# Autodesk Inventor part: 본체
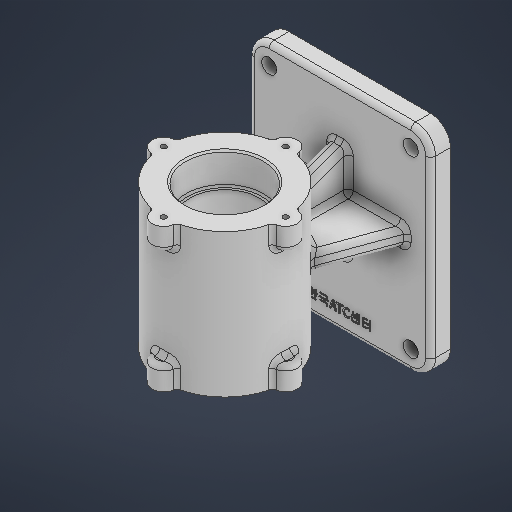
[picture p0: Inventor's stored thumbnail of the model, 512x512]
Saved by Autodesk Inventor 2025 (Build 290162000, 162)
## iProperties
Created: 2025-08
Part Number: 본체
Material: 일반
Document SubType Name: Modeling
Designer: infra14
Density: 1 g/cm^3
Appearance: 기본값
Author: infra14
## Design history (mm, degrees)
sketch "스케치1"
  geometry: L1 (55, -65)-(-55, -65); L2 (-55, -65)-(-55, 65); L3 (-55, 65)-(55, 65); L4 (55, 65)-(55, -65); L5 (55, -65)-(-55, 65); L6 (-55, -65)-(55, 65); 1 further point
  constraints: 12 end point, 2 midpoint, 2 parallel, 1 horizontal, 1 perpendicular
  dimensions: "d0" = 110 distance of L2.end L3.end; "d1" = 130 distance of L1.end L2.end
extrude "돌출1" new body sketch "스케치1" distance "d2" = 12; taper "d3" = 0 deg
sketch "스케치2"
  geometry: L1 (43, -53)-(-43, -53); L2 (-43, -53)-(-43, 53); L3 (-43, 53)-(43, 53); L4 (43, 53)-(43, -53); L5 (43, -53)-(-43, 53); L6 (-43, -53)-(43, 53); C1 r 4.5 at (-43, 53); C2 r 4.5 at (43, 53); C3 r 4.5 at (-43, -53); C4 r 4.5 at (43, -53); 1 further point
  constraints: 12 end point, 4 centre point, 4 coincident, 2 midpoint, 2 parallel, 1 horizontal, 1 perpendicular
  dimensions: "d4" = 86 distance of L2.end L3.end; "d5" = 106 distance of L1.end L2.end; "d6" = 9 diameter of C1; "d7" = 9 diameter of C2; "d8" = 9 diameter of C3; "d9" = 9 diameter of C4
extrude "돌출2" cut sketch "스케치2" distance "d10" = 12; taper "d11" = 0 deg
sketch "스케치3"
  geometry: L1 (29.5, 82)-(-19.5, 82); L2 (-19.5, 82)-(-19.5, 103); L3 (-19.5, 103)-(29.5, 103); L4 (29.5, 103)-(29.5, 82); L5 (-65, 0)-(-65, 12) reference; L6 (-65, 0)-(65, 0) reference; L7 (-19.5, 82)-(-38.5, 82); L8 (-38.5, 82)-(-38.5, 105.5); L9 (-38.5, 105.5)-(-19.5, 105.5); L10 (-19.5, 105.5)-(-19.5, 82); L11 (29.5, 82)-(48.5, 82); L12 (48.5, 82)-(48.5, 105.5); L13 (48.5, 105.5)-(29.5, 105.5); L14 (29.5, 105.5)-(29.5, 82); L15 (-38.5, 82)-(48.5, 82); L16 (48.5, 82)-(48.5, 119); L17 (48.5, 119)-(-38.5, 119); L18 (-38.5, 119)-(-38.5, 82); 7 further points
  constraints: 32 end point, 8 parallel, 4 horizontal, 4 perpendicular, 2 midpoint
  dimensions: "d12" = 49 distance of L2.end L3.end; "d13" = 21 distance of L1.end L2.end; "d14" = 70 distance from line of point (5, 103) L5; "d16" = 19 distance of L8.end L9.end; "d17" = 23.5 distance of L7.end L8.end; "d18" = 19 distance of L13.end L12.end; "d19" = 23.5 distance of L12.end L11.end; "d20" = 37 distance of L16.end L15.end; "d64" = 82 distance from line of L6 L1.start
revolve "회전1" sketch "스케치3" stored, may be unused: angle "d21" = 90 deg
sketch "스케치4"
  geometry: C1 r 7 at (0, 37); C2 r 7 at (-37, 0); C3 r 7 at (0, -37); C4 r 7 at (37, 0); 10 further points
  constraints: 4 centre point, 1 vertical alignment, 11 other
  dimensions: "d22" = 14 diameter of C1; "d25" = 360 deg dimension on point (0, 0) C1.centre (derived)
extrude "돌출3" join sketch "스케치4" distance "d27" = 14; taper "d28" = 0 deg
sketch "스케치6"
  geometry: A1 r 7 centre (0, -37) between (-6.969, -36.338) and (6.969, -36.338) reference; A2 r 7 centre (37, 0) between (36.338, -6.969) and (36.338, 6.969) reference; A3 r 7 centre (-37, 0) between (-36.338, 6.969) and (-36.338, -6.969) reference; A4 r 7 centre (0, 37) between (6.969, 36.338) and (-6.969, 36.338) reference; 2 further points
  constraints: 1 other
extrude "돌출4" join sketch "스케치6" distance "d29" = 14; taper "d30" = 0 deg
sketch "스케치8"
  geometry: A1 r 37 centre (0, 37) between (-6.969, 0.662) and (6.969, 0.662) reference; A2 r 37 centre (0, 37) between (36.338, 30.031) and (36.338, 43.969) reference; A3 r 37 centre (0, 37) between (6.969, 73.338) and (-6.969, 73.338) reference; A4 r 37 centre (0, 37) between (-36.338, 43.969) and (-36.338, 30.031) reference; 5 further points
  constraints: 8 point on circle
hole "구멍1" sketch "스케치8" at (0, 0), (37, 37), (0, 74), (-37, 37) diameter "d31" = 3.242; stored, may be unused: countersink angle "d35" = 90 deg, drill point angle "d37" = 118 deg; dims "d32" = 8, "d33" = 4, "d34" = 2, "d36" = 10
sketch "스케치9"
  geometry: A1 r 37 centre (0, -37) between (-6.969, -73.338) and (6.969, -73.338) reference; A2 r 37 centre (0, -37) between (-36.338, -30.031) and (-36.338, -43.969) reference; A3 r 7 centre (0, 0) between (6.969, -0.662) and (-6.969, -0.662) reference; A4 r 37 centre (0, -37) between (6.969, -0.662) and (-6.969, -0.662) reference; A5 r 37 centre (0, -37) between (36.338, -43.969) and (36.338, -30.031) reference; 5 further points
  constraints: 6 point on circle, 1 coincident
hole "구멍2" sketch "스케치9" at (0, -74), (-37, -37), (0, 0), (37, -37) diameter "d38" = 3.242; stored, may be unused: countersink angle "d42" = 90 deg, drill point angle "d44" = 118 deg; dims "d39" = 8, "d40" = 4, "d41" = 2, "d43" = 10
sketch "스케치11"
  geometry: L1 (34.5, 45)-(-24.5, 45) reference; L2 (-12.989, 45)-(-25, 12); L3 (65, 12)-(-65, 12) reference; L4 (35, 12)-(22.989, 45); L5 (-12.989, 45)-(22.989, 45); 2 further points
  constraints: 6 end point, 4 point on line, 2 midpoint, 1 collinear
  dimensions: "d45" = 110 deg angle of L3 L2; "d46" = 110 deg angle of L3 L4; "d47" = 60 distance of L4.start L2.end
extrude "돌출5" join sketch "스케치11" stored distance "d48" = 10; taper "d49" = 0 deg
node "작업 평면1"
sketch "스케치15"
  geometry: L1 (14, 12)-(29.664, 55.036); L2 (0, 0)-(110, 0) reference; L3 (0, 12)-(110, 12) reference; L4 (50, 45)-(50, 12) reference; L5 (50, 12)-(50, 45) reference; A1 r 37 centre (55, 82) between (48.031, 45.662) and (61.969, 45.662) reference; A2 r 37 centre (55, 82) between (18.662, 75.031) and (48.031, 45.662) reference; A3 r 37 centre (55, 82) between (18.662, 88.969) and (18.662, 75.031) reference; A4 r 37 centre (55, 82) between (48.031, 118.338) and (18.662, 88.969) reference; A5 r 37 centre (55, 82) between (61.969, 118.338) and (48.031, 118.338) reference; A6 r 37 centre (55, 82) between (91.338, 88.969) and (61.969, 118.338) reference; A7 r 37 centre (55, 82) between (91.338, 75.031) and (91.338, 88.969) reference; A8 r 37 centre (55, 82) between (61.969, 45.662) and (91.338, 75.031) reference; A9 r 37 centre (55, 82) between (18.662, 88.969) and (18.662, 75.031) reference; A10 r 37 centre (55, 82) between (18.662, 75.031) and (48.031, 45.662) reference; A11 r 37 centre (55, 82) between (48.031, 45.662) and (61.969, 45.662) reference; A12 r 37 centre (55, 82) between (61.969, 45.662) and (91.338, 75.031) reference; A13 r 37 centre (55, 82) between (91.338, 75.031) and (91.338, 88.969) reference; A14 r 37 centre (55, 82) between (91.338, 88.969) and (61.969, 118.338) reference; A15 r 37 centre (55, 82) between (61.969, 118.338) and (48.031, 118.338) reference; A16 r 37 centre (55, 82) between (48.031, 118.338) and (18.662, 88.969) reference; 3 further points
  constraints: 2 end point, 1 point on circle
  dimensions: "d55" = 12 distance from line of L2 L1.start; "d56" = 70 deg angle of L3 L1; "d57" = 14 distance of L3.start L1.start
feature "리브1" sketch "스케치15" dims "d58" = 1, "d59" = 10, "d60" = 0, "d61" = 0, "d62" = 1, "d63" = 1
feature "면 삭제1"
feature "면 삭제2"
fillet "모깎기1" dims "d65" = 12
feature "면 삭제3"
feature "면 삭제4"
fillet "모깎기2" dims "d66" = 3
fillet "모깎기3" dims "d67" = 3
fillet "모깎기4" dims "d68" = 3
fillet "모깎기5" dims "d69" = 1
fillet "모깎기6" dims "d70" = 3
chamfer "모따기1" distance "d71" = 1; stored, may be unused: second distance "d72" = 2, angle "d73" = 45 deg
chamfer "모따기2" distance "d74" = 1; stored, may be unused: second distance "d75" = 2, angle "d76" = 45 deg
fillet "모깎기7" dims "d77" = 3
sketch "스케치16"
  geometry: L1 (-12.279, -65)-(12.279, -65); L2 (12.279, -65)-(12.279, -41); L3 (12.279, -41)-(-12.279, -41); L4 (-12.279, -41)-(-12.279, -65); L5 (43.101, 3)-(43.101, 7) reference; L6 (-43, -65)-(43, -65) reference; 4 further points
  constraints: 4 midpoint, 2 other
  dimensions: "d78" = 58 vertical distance of point (12.279, -53) point (43.101, 5)
feature "엠보싱1" sketch "스케치16" dims "d0" = 110, "d1" = 130, "d79" = 0.5, "d80" = 0
node "솔리드1"
mirror "미러1"
node "스케치 - 원형 패턴1" dims "d25" = 360 deg (derived)
node "투영된 루프4"
node "투영된 루프5"
feature "A9D066F2-1C7D-4E18-AEED-F7BC21143FA4" dims "d31" = 3.242, "d32" = 8, "d33" = 4, "d34" = 2, "d35" = 90 deg, "d36" = 10, "d37" = 118 deg
